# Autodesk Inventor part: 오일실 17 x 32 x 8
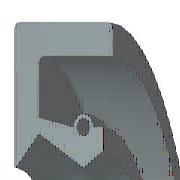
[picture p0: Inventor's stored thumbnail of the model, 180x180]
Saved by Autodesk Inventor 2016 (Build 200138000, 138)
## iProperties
IsCustomPart: 1
Created: 2012-02
Part Number: 오일실 17 x 32 x 8
Material: 고무
Description: 오일-실
Document SubType Name: Modeling
Standard: KS B 2804
Designer: mduedu
Standards Organization: KS
Language: ko-KR
Size Designation: D - 17 32 8
Categories: <MemberInstance><Categories><Category DisplayName="샤프트 부품" InternalName="7f7aeb1f-a693-4053-b835-cee3144e0d98" Mnemonic="SHFT"><Category DisplayName="실링" Intern
Density: 0.93 g/cm^3
Appearance: 고무 - 검은색 - 버전 1.1
Author: mduedu
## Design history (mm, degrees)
revolve "본체" stored, may be unused: angle "d17" = 90 deg
revolve "스프링1" stored, may be unused: angle "d18" = 90 deg
body "Solid1"
sketch "스케치1"
  geometry: L1 (0, 16)-(8, 16); L2 (8, 14.25)-(1.75, 14.25); L3 (1.75, 10.25)-(4.9, 8.5); L4 (4.9, 8.5)-(0, 8.5); L5 (0, 0)-(9.586, 0) reference; L6 (4.9, 8.5)-(6.3, 9.375); L7 (0, 18)-(0, -3) reference; L8 (-1.941, 0)-(11.507, 0) reference; L9 (4.2, 10.6)-(1.75, 11.21); L10 (1.75, 11.21)-(1.75, 14.25); L11 (0, 16)-(0, 8.588); L12 (4.9, 8.5)-(0, 8.5); L13 (1.75, 10.25)-(0.152, 8.528); L14 (8, 16)-(8, 14.25); L15 (5.6, 10.6)-(6.3, 10.6); L16 (6.3, 10.6)-(6.3, 9.375); C1 r 0.455 at (4.9, 10.6); A1 r 0.7 centre (4.9, 10.6) between (5.6, 10.6) and (4.2, 10.6); A2 r 0.088 centre (0.088, 8.588) between (0, 8.588) and (0.152, 8.528); 1 further point
  constraints: 28 end point, 5 horizontal alignment, 5 point on line, 4 point on circle, 4 vertical alignment, 3 centre point, 3 tangent, 2 collinear, 2 horizontal, 2 perpendicular, 1 coincident, 1 parallel
  dimensions: "d0" = 32 diameter of L1 L5 (= SD2); "d1" = 1.75 distance of L1.end L2.start (= SD); "d2" = 0.91 diameter of C1 (= SPDI); "d3" = 1.4 diameter of A1 (= SPDA); "d4" = 17 diameter of L3.end L5 (= NND); "d5" = 20.5 diameter of L3.start L5 (= TKDM); "d7" = 22.42 diameter of L9.end L5 (= TKDM + 0.24 x SWDT); "d8" = 1.75 distance between parallel lines of L11 L10 (= SD); "d9" = 4.9 distance from line of L11 C1.centre (= SPDST); "d10" = 21.2 diameter of C1.centre L5 (= HLDM); "d11" = 0.0875 radius of A2 (= 0.25 x LAB); "d12" = 6.3 distance between parallel lines of L11 L16 (= SDI); "d13" = 18.75 diameter of L6.end L5 (= ABDM); "d14" = 8 distance from line of L11 L1.end (= SWDT)
fillet "모깎기1" dims "d6" = 0.3 (= RR)
other parameters: "SD2" = 32 [user parameter; used in 1 equation term], "SWDT" = 8 [user parameter; used in 2 equation terms], "RR" = 0.3 [user parameter; used in 1 equation term], "SD" = 1.75 [user parameter; used in 2 equation terms], "NND" = 17 [user parameter; used in 1 equation term], "SPDA" = 1.4 [user parameter; used in 1 equation term], "SPDI" = 0.91 [user parameter; used in 1 equation term], "TKDM" = 20.5 [user parameter; used in 2 equation terms], "HLDM" = 21.2 [user parameter; used in 1 equation term], "ABDM" = 18.75 [user parameter; used in 1 equation term], "SDI" = 6.3 [user parameter; used in 1 equation term], "SPDST" = 4.9 [user parameter; used in 1 equation term], "LAB" = 0.35 [user parameter; used in 1 equation term], "d15" = 0, "d16" = 0, "d19" = 0
